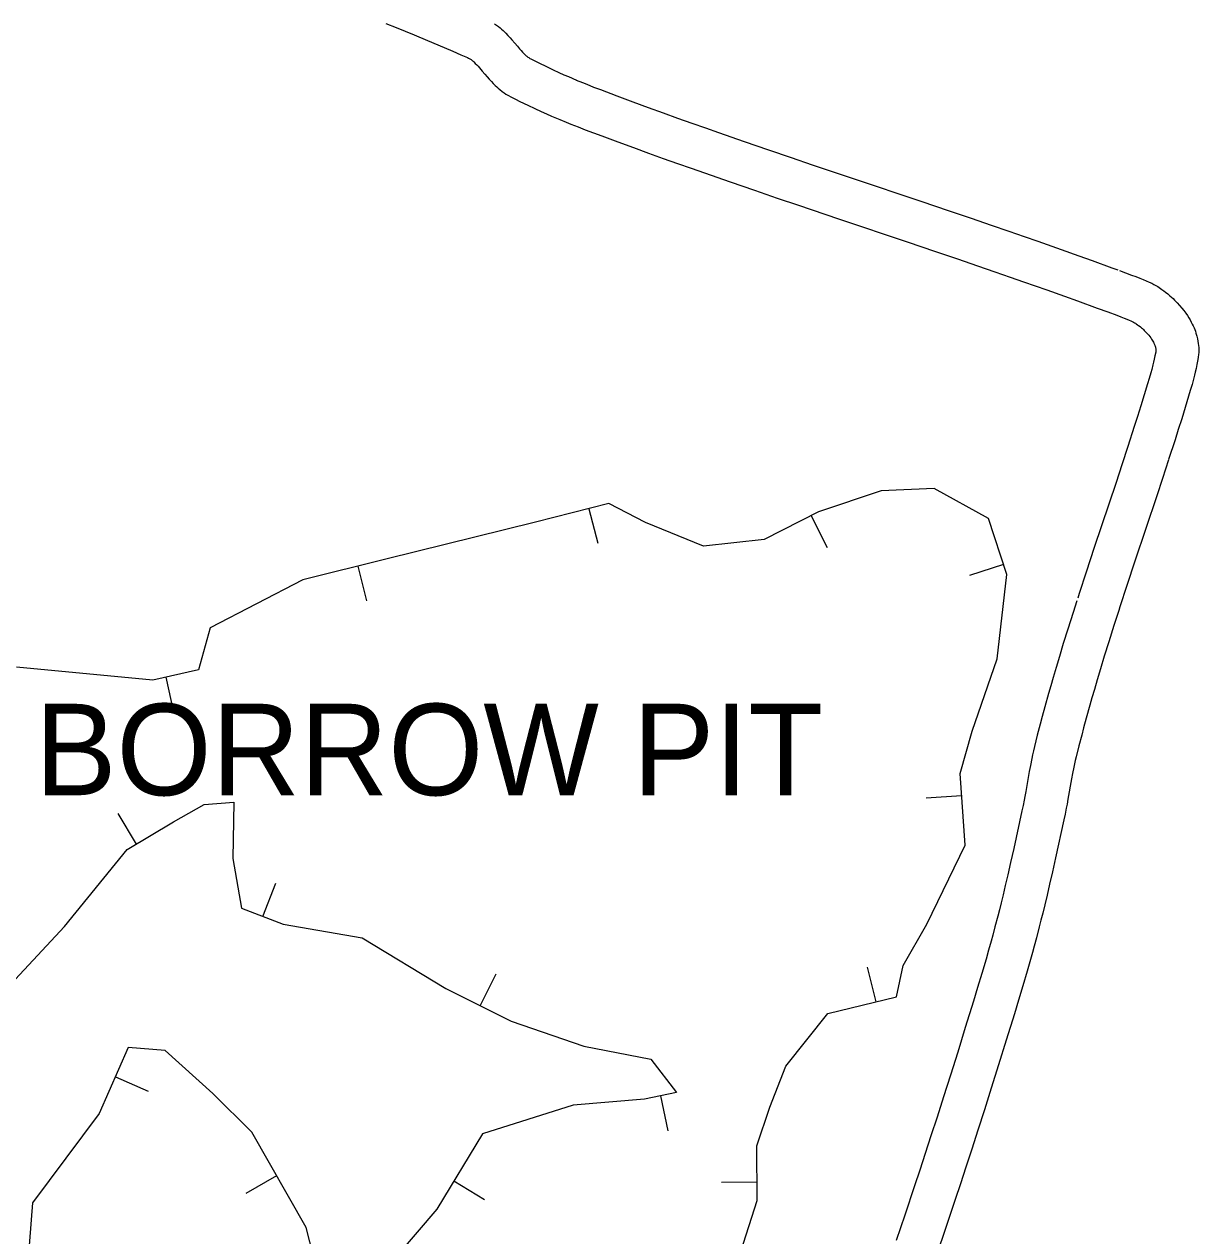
# Model space of a CAD drawing. Extents: x 3177185 to 3215018, y 812988 to 838321.
# Drawn here: x 3194281 to 3195103, y 831437 to 832285 of the extents above; entities that cross this region are included whole.
import ezdxf

# ---------------------------------------------------------------- set-up
doc = ezdxf.new("R2010")
doc.units = 0
for name, color, linetype in [('V-BORW-IDEN', 7, 'Continuous'), ('V-BORW-LINE', 7, 'Continuous'), ('V-ROAD-CNTR', 7, 'Continuous')]:
    doc.layers.add(name, color=color, linetype=linetype)

msp = doc.modelspace()

# ---------------------------------------------------------------- linework, layer by layer
at = {"layer": 'V-BORW-LINE'}
for p, q in [((3194676.56, 831945.76), (3194682.74, 831921.54)), ((3194676.56, 831945.76), (3194682.74, 831921.54)), ((3194832.07, 831940.84), (3194843.35, 831918.53)), ((3194832.07, 831940.84), (3194843.35, 831918.53)), ((3194514.89, 831905.53), (3194520.94, 831881.28)), ((3194514.89, 831905.53), (3194520.94, 831881.28)), ((3194966.78, 831906.62), (3194943, 831898.9)), ((3194966.78, 831906.62), (3194943, 831898.9)), ((3194380.53, 831827.86), (3194385.94, 831803.46)), ((3194380.53, 831827.86), (3194385.94, 831803.46)), ((3194937.39, 831744.91), (3194912.46, 831743.1)), ((3194937.39, 831744.91), (3194912.46, 831743.1)), ((3194359.85, 831711.08), (3194347.05, 831732.56)), ((3194359.85, 831711.08), (3194347.05, 831732.56)), ((3194448.4, 831660.42), (3194457.36, 831683.76)), ((3194448.4, 831660.42), (3194457.36, 831683.76)), ((3194877.47, 831600.77), (3194871.56, 831625.06)), ((3194877.47, 831600.77), (3194871.56, 831625.06)), ((3194600.46, 831597.98), (3194611.61, 831620.36)), ((3194600.46, 831597.98), (3194611.61, 831620.36)), ((3194345.2, 831548.3), (3194368.06, 831538.19)), ((3194345.2, 831548.3), (3194368.06, 831538.19)), ((3194726.6, 831534.92), (3194731.74, 831510.45)), ((3194726.6, 831534.92), (3194731.74, 831510.45)), ((3194458.04, 831478.95), (3194436.35, 831466.53)), ((3194458.04, 831478.95), (3194436.35, 831466.53)), ((3194582.08, 831475.43), (3194603.47, 831462.49)), ((3194582.08, 831475.43), (3194603.47, 831462.49)), ((3194794.24, 831474.62), (3194769.24, 831474.36)), ((3194794.24, 831474.62), (3194769.24, 831474.36))]:
    msp.add_line(p, q, dxfattribs=at)
for points in [[(3194782.97, 831425.92), (3194794.37, 831461.77), (3194793.98, 831499.99), (3194803.15, 831527.04), (3194814.27, 831555.74), (3194843.7, 831592.56), (3194891.78, 831604.25), (3194896.37, 831626.03), (3194913.03, 831654.94), (3194939.91, 831710.27), (3194936.27, 831760.36), (3194944.75, 831790.18), (3194962.19, 831840.8), (3194969.03, 831899.69), (3194956.29, 831938.95), (3194918.08, 831959.79), (3194881.04, 831958.21), (3194837.27, 831943.47), (3194799.31, 831924.28), (3194756.86, 831919.59), (3194716.22, 831935.98), (3194690.5, 831949.32), (3194639.23, 831936.24), (3194596.71, 831925.93), (3194535.38, 831910.64), (3194476.27, 831895.9), (3194411.54, 831862.37), (3194403.26, 831832.9), (3194371.42, 831825.84), (3194276.05, 831834.78)], [(3194782.97, 831425.92), (3194794.37, 831461.77), (3194793.98, 831499.99), (3194803.15, 831527.04), (3194814.27, 831555.74), (3194843.7, 831592.56), (3194891.78, 831604.25), (3194896.37, 831626.03), (3194913.03, 831654.94), (3194939.91, 831710.27), (3194936.27, 831760.36), (3194944.75, 831790.18), (3194962.19, 831840.8), (3194969.03, 831899.69), (3194956.29, 831938.95), (3194918.08, 831959.79), (3194881.04, 831958.21), (3194837.27, 831943.47), (3194799.31, 831924.28), (3194756.86, 831919.59), (3194716.22, 831935.98), (3194690.5, 831949.32), (3194639.23, 831936.24), (3194596.71, 831925.93), (3194535.38, 831910.64), (3194476.27, 831895.9), (3194411.54, 831862.37), (3194403.26, 831832.9), (3194371.42, 831825.84), (3194276.05, 831834.78)], [(3194782.97, 831425.92), (3194794.37, 831461.77), (3194793.98, 831499.99), (3194803.15, 831527.04), (3194814.27, 831555.74), (3194843.7, 831592.56), (3194891.78, 831604.25), (3194896.37, 831626.03), (3194913.03, 831654.94), (3194939.91, 831710.27), (3194936.27, 831760.36), (3194944.75, 831790.18), (3194962.19, 831840.8), (3194969.03, 831899.69), (3194956.29, 831938.95), (3194918.08, 831959.79), (3194881.04, 831958.21), (3194837.27, 831943.47), (3194799.31, 831924.28), (3194756.86, 831919.59), (3194716.22, 831935.98), (3194690.5, 831949.32), (3194639.23, 831936.24), (3194596.71, 831925.93), (3194535.38, 831910.64), (3194476.27, 831895.9), (3194411.54, 831862.37), (3194403.26, 831832.9), (3194371.42, 831825.84), (3194276.05, 831834.78)], [(3194275.08, 831616.43), (3194309.51, 831653.31), (3194353.52, 831707.32), (3194385.85, 831726.58), (3194407.3, 831738.7), (3194428.11, 831740.35), (3194427.32, 831700.96), (3194433.33, 831666.2), (3194462.66, 831654.95), (3194517.8, 831645.41), (3194576.46, 831609.93), (3194622.22, 831587.15), (3194673.12, 831569.78), (3194719.94, 831560.52), (3194737.82, 831537.27), (3194715.41, 831532.57), (3194665.47, 831528.37), (3194602.06, 831508.44), (3194570.12, 831455.67), (3194510.77, 831386.34)], [(3194275.08, 831616.43), (3194309.51, 831653.31), (3194353.52, 831707.32), (3194385.85, 831726.58), (3194407.3, 831738.7), (3194428.11, 831740.35), (3194427.32, 831700.96), (3194433.33, 831666.2), (3194462.66, 831654.95), (3194517.8, 831645.41), (3194576.46, 831609.93), (3194622.22, 831587.15), (3194673.12, 831569.78), (3194719.94, 831560.52), (3194737.82, 831537.27), (3194715.41, 831532.57), (3194665.47, 831528.37), (3194602.06, 831508.44), (3194570.12, 831455.67), (3194510.77, 831386.34)], [(3194275.08, 831616.43), (3194309.51, 831653.31), (3194353.52, 831707.32), (3194385.85, 831726.58), (3194407.3, 831738.7), (3194428.11, 831740.35), (3194427.32, 831700.96), (3194433.33, 831666.2), (3194462.66, 831654.95), (3194517.8, 831645.41), (3194576.46, 831609.93), (3194622.22, 831587.15), (3194673.12, 831569.78), (3194719.94, 831560.52), (3194737.82, 831537.27), (3194715.41, 831532.57), (3194665.47, 831528.37), (3194602.06, 831508.44), (3194570.12, 831455.67), (3194510.77, 831386.34)], [(3194489, 831402.73), (3194478.69, 831442.9), (3194440.58, 831509.44), (3194413.48, 831536.58), (3194380.07, 831566.56), (3194354.2, 831568.66), (3194333.84, 831522.62), (3194287.26, 831460.01), (3194283.84, 831418.19)], [(3194489, 831402.73), (3194478.69, 831442.9), (3194440.58, 831509.44), (3194413.48, 831536.58), (3194380.07, 831566.56), (3194354.2, 831568.66), (3194333.84, 831522.62), (3194287.26, 831460.01), (3194283.84, 831418.19)], [(3194489, 831402.73), (3194478.69, 831442.9), (3194440.58, 831509.44), (3194413.48, 831536.58), (3194380.07, 831566.56), (3194354.2, 831568.66), (3194333.84, 831522.62), (3194287.26, 831460.01), (3194283.84, 831418.19)]]:
    msp.add_lwpolyline(points, dxfattribs=at)
at = {"layer": 'V-ROAD-CNTR'}
for points in [[(3194534.52, 832285.36), (3194541.7, 832282.43), (3194554.29, 832277.24), (3194563.7, 832273.31), (3194570.74, 832270.35), (3194581.31, 832265.86), (3194587.03, 832263.4)], [(3194610.57, 832285.09), (3194611.95, 832284.11), (3194613.23, 832283.14), (3194614.41, 832282.17), (3194615.49, 832281.23), (3194616.56, 832280.27), (3194618.33, 832278.55), (3194619.93, 832276.88), (3194621.34, 832275.34), (3194622.6, 832273.91), (3194624.73, 832271.41), (3194626.49, 832269.33), (3194627.94, 832267.64), (3194629.14, 832266.28), (3194630.13, 832265.19), (3194630.97, 832264.32), (3194631.68, 832263.63), (3194632.26, 832263.09), (3194632.76, 832262.64), (3194633.12, 832262.34), (3194633.92, 832261.72), (3194634.41, 832261.36), (3194634.69, 832261.17), (3194635.26, 832260.82), (3194635.91, 832260.47), (3194638.74, 832259.04), (3194641.51, 832257.66), (3194646.81, 832255.09), (3194651.45, 832252.91), (3194655.53, 832251.04), (3194659.11, 832249.43), (3194662.24, 832248.06), (3194667.87, 832245.66)], [(3194587.03, 832263.4), (3194591.69, 832261.4), (3194592.31, 832261.11), (3194592.76, 832260.87), (3194593.21, 832260.6), (3194593.67, 832260.3), (3194594.14, 832259.97), (3194594.61, 832259.61), (3194595.09, 832259.22), (3194595.58, 832258.79), (3194596.01, 832258.4), (3194597.07, 832257.37), (3194598.05, 832256.35), (3194599.01, 832255.3), (3194599.94, 832254.25), (3194601.86, 832252), (3194603.63, 832249.91), (3194605.29, 832247.97), (3194606.85, 832246.2), (3194608.31, 832244.61), (3194609.66, 832243.21), (3194610.92, 832241.97), (3194612.09, 832240.88), (3194613.15, 832239.94), (3194614.18, 832239.07), (3194615.89, 832237.73), (3194617.33, 832236.69), (3194618.53, 832235.89), (3194620.25, 832234.84), (3194621.96, 832233.91), (3194625.28, 832232.23), (3194628.28, 832230.73), (3194633.87, 832228.02), (3194638.81, 832225.7), (3194643.15, 832223.71), (3194646.96, 832222), (3194650.32, 832220.53), (3194656.1, 832218.07)], [(3194667.73, 832245.72), (3194671.97, 832243.96), (3194675.09, 832242.69), (3194679.84, 832240.82), (3194684.61, 832238.98), (3194696.07, 832234.67), (3194707.2, 832230.53), (3194718, 832226.57), (3194728.48, 832222.76), (3194738.64, 832219.11), (3194748.49, 832215.6), (3194758.04, 832212.22), (3194767.3, 832208.97), (3194785.28, 832202.71), (3194802.15, 832196.91), (3194817.99, 832191.5), (3194832.85, 832186.46), (3194860.76, 832177.05), (3194909.66, 832160.61), (3194928.01, 832154.41), (3194944.08, 832148.95), (3194958.13, 832144.15), (3194970.43, 832139.91), (3194981.19, 832136.19), (3194990.61, 832132.9), (3195007.07, 832127.1), (3195019.41, 832122.71), (3195028.67, 832119.38), (3195042.54, 832114.33), (3195046.65, 832112.82)], [(3194656.24, 832218), (3194660.6, 832216.2), (3194663.94, 832214.84), (3194668.94, 832212.87), (3194673.95, 832210.94), (3194685.56, 832206.57), (3194696.81, 832202.39), (3194707.71, 832198.39), (3194718.28, 832194.55), (3194728.52, 832190.87), (3194738.45, 832187.33), (3194748.07, 832183.92), (3194757.4, 832180.65), (3194775.47, 832174.36), (3194792.43, 832168.53), (3194808.33, 832163.1), (3194823.24, 832158.04), (3194851.18, 832148.62), (3194900.08, 832132.18), (3194918.39, 832125.99), (3194934.4, 832120.56), (3194948.4, 832115.77), (3194960.64, 832111.56), (3194971.34, 832107.85), (3194980.69, 832104.59), (3194997.05, 832098.83), (3195009.3, 832094.46), (3195018.47, 832091.16), (3195032.23, 832086.16), (3195039.71, 832083.4)], [(3195047.95, 832112.34), (3195056.38, 832109.23), (3195059.34, 832108.14), (3195062, 832107.13), (3195064.43, 832106.17), (3195066.63, 832105.24), (3195068.61, 832104.33), (3195070.39, 832103.47), (3195071.97, 832102.64), (3195073.37, 832101.86), (3195074.59, 832101.14), (3195075.74, 832100.43), (3195077.55, 832099.22), (3195078.98, 832098.2), (3195080.1, 832097.35), (3195081.66, 832096.11), (3195083.18, 832094.79), (3195084.32, 832093.76), (3195085.36, 832092.78), (3195086.41, 832091.76), (3195088.25, 832089.86), (3195089.97, 832087.98), (3195091.53, 832086.14), (3195092.94, 832084.37), (3195094.21, 832082.64), (3195095.35, 832080.99), (3195096.37, 832079.39), (3195097.29, 832077.85), (3195098.11, 832076.37), (3195098.83, 832074.96), (3195099.48, 832073.6), (3195100.05, 832072.29), (3195100.55, 832071.06), (3195100.99, 832069.87), (3195101.4, 832068.64), (3195102.01, 832066.59), (3195102.48, 832064.63), (3195102.81, 832062.9), (3195103.04, 832061.35), (3195103.19, 832059.97), (3195103.29, 832058.64), (3195103.35, 832056.64), (3195103.31, 832054.99), (3195103.23, 832053.66), (3195103.04, 832051.87), (3195102.76, 832050.12), (3195102.09, 832046.72), (3195101.47, 832043.85), (3195100.89, 832041.36), (3195100.35, 832039.17), (3195099.39, 832035.45), (3195098.62, 832032.64), (3195097.44, 832028.54), (3195096.23, 832024.49), (3195093.78, 832016.47), (3195091.38, 832008.74), (3195089.03, 832001.26), (3195086.72, 831994.02), (3195082.23, 831980.08)], [(3195039.71, 832083.4), (3195045.99, 832081.09), (3195048.84, 832080.03), (3195051.17, 832079.15), (3195053.05, 832078.41), (3195054.57, 832077.77), (3195055.81, 832077.2), (3195056.84, 832076.7), (3195057.7, 832076.25), (3195058.44, 832075.84), (3195059.06, 832075.47), (3195059.53, 832075.18), (3195060.53, 832074.51), (3195061.21, 832074.03), (3195061.67, 832073.68), (3195062.47, 832073.04), (3195063.29, 832072.33), (3195063.95, 832071.73), (3195064.62, 832071.1), (3195065.2, 832070.54), (3195066.41, 832069.3), (3195067.44, 832068.17), (3195068.33, 832067.11), (3195069.11, 832066.13), (3195069.78, 832065.23), (3195070.35, 832064.39), (3195070.85, 832063.61), (3195071.27, 832062.91), (3195071.62, 832062.27), (3195071.93, 832061.68), (3195072.18, 832061.15), (3195072.39, 832060.67), (3195072.57, 832060.22), (3195072.71, 832059.83), (3195072.8, 832059.57), (3195073.03, 832058.81), (3195073.15, 832058.3), (3195073.23, 832057.88), (3195073.28, 832057.52), (3195073.31, 832057.23), (3195073.32, 832057.1), (3195073.34, 832056.55), (3195073.33, 832056.27), (3195073.33, 832056.17), (3195073.29, 832055.8), (3195073.22, 832055.39), (3195072.71, 832052.81), (3195072.2, 832050.44), (3195071.71, 832048.33), (3195071.26, 832046.51), (3195070.4, 832043.18), (3195069.73, 832040.73), (3195068.65, 832036.96), (3195067.51, 832033.17), (3195065.11, 832025.31), (3195062.74, 832017.69), (3195060.42, 832010.31), (3195058.15, 832003.17), (3195053.68, 831989.29)], [(3195053.7, 831989.35), (3195049.44, 831976.35), (3195045.43, 831964.2), (3195030.22, 831918.53), (3195024.54, 831901.36), (3195019.62, 831886.3), (3195018.64, 831883.22)], [(3195082.21, 831980.02), (3195077.94, 831966.98), (3195073.9, 831954.75), (3195058.69, 831909.08), (3195053.04, 831891.99), (3195048.16, 831877.05), (3195047.38, 831874.62)], [(3195018.05, 831881.4), (3195015.38, 831873.08), (3195011.72, 831861.49), (3195008.56, 831851.33), (3195005.85, 831842.41), (3195003.51, 831834.59), (3195001.5, 831827.73), (3194999.76, 831821.73), (3194998.25, 831816.44), (3194995.68, 831807.22), (3194993.79, 831800.28), (3194992.39, 831795.04), (3194990.35, 831787.2), (3194988.35, 831779.3), (3194987.64, 831776.35), (3194987.02, 831773.56), (3194986.46, 831770.93), (3194985.51, 831766.15), (3194984.73, 831761.95), (3194982.26, 831747.79), (3194981.64, 831744.35), (3194981.17, 831741.83), (3194980.43, 831738.06), (3194979.63, 831734.29), (3194973.82, 831708.05), (3194971.62, 831698.23), (3194969.67, 831689.66), (3194967.94, 831682.19), (3194966.39, 831675.66), (3194965.01, 831669.97), (3194963.78, 831665), (3194962.7, 831660.68), (3194960.73, 831653.1), (3194959.22, 831647.44), (3194958.07, 831643.22), (3194956.29, 831636.89), (3194954.45, 831630.56), (3194951.43, 831620.44), (3194948.49, 831610.62), (3194945.61, 831601.12), (3194939.98, 831582.71), (3194934.64, 831565.49), (3194929.57, 831549.36), (3194924.78, 831534.26), (3194920.24, 831520.11), (3194915.95, 831506.87), (3194911.9, 831494.46), (3194908.08, 831482.83), (3194904.47, 831471.94), (3194897.65, 831451.53), (3194891.63, 831433.69)], [(3195047.38, 831874.62), (3195043.96, 831863.98), (3195040.35, 831852.53), (3195037.24, 831842.52), (3195034.57, 831833.74), (3195032.27, 831826.06), (3195030.3, 831819.34), (3195028.59, 831813.45), (3195027.13, 831808.3), (3195024.6, 831799.25), (3195022.76, 831792.47), (3195021.4, 831787.39), (3195019.41, 831779.74), (3195017.48, 831772.11), (3195016.86, 831769.54), (3195016.32, 831767.14), (3195015.84, 831764.89), (3195014.97, 831760.49), (3195014.25, 831756.64), (3195011.8, 831742.56), (3195011.15, 831738.95), (3195010.64, 831736.19), (3195009.82, 831732.04), (3195008.95, 831727.93), (3195003.11, 831701.53), (3195000.89, 831691.62), (3194998.91, 831682.93), (3194997.14, 831675.33), (3194995.56, 831668.67), (3194994.15, 831662.84), (3194992.89, 831657.74), (3194991.76, 831653.26), (3194989.75, 831645.47), (3194988.19, 831639.62), (3194986.98, 831635.21), (3194985.13, 831628.63), (3194983.22, 831622.08), (3194980.18, 831611.84), (3194977.21, 831601.96), (3194974.31, 831592.38), (3194968.65, 831573.88), (3194963.27, 831556.55), (3194958.18, 831540.33), (3194953.36, 831525.14), (3194948.79, 831510.91), (3194944.48, 831497.59), (3194940.41, 831485.12), (3194936.57, 831473.43), (3194932.94, 831462.48), (3194926.09, 831441.98), (3194920.05, 831424.06)]]:
    msp.add_lwpolyline(points, dxfattribs=at)

# ---------------------------------------------------------------- texts
at = {"layer": 'V-BORW-IDEN'}
msp.add_text('BORROW PIT', height=64, dxfattribs=at).set_placement((3194288.87, 831745.26))

doc.saveas('drawing.dxf')
